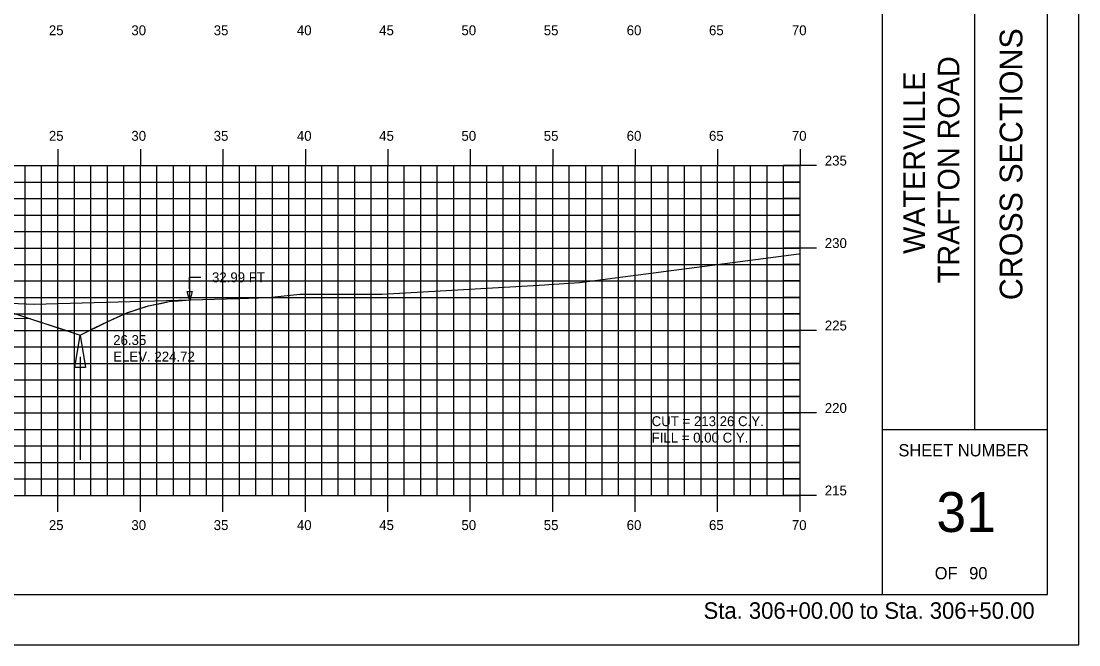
# Model space of a CAD drawing. Extents: x 1137433 to 1137603, y 608981 to 609091.
# Drawn here: x 1137538.4 to 1137602.6, y 608981.3 to 609019.1 of the extents above; entities that cross this region are included whole.
import ezdxf

# ---------------------------------------------------------------- set-up
doc = ezdxf.new("R2010")
doc.units = 0
for name, color, linetype in [('BORDER', 7, 'Continuous'), ('D_Drainage_Ditch_Line', 7, 'Continuous'), ('D_Roadway_SlopeLines', 7, 'Continuous'), ('D_Roadway_SubGrade', 7, 'Continuous'), ('D_Text_Standard', 7, 'Continuous'), ('H_V ANNOTATION', 7, 'Continuous'), ('HIGHWAY_TITLE', 7, 'Continuous'), ('MAJOR', 7, 'Continuous'), ('MINOR', 7, 'Continuous'), ('PLOT BOUNDARY', 7, 'Continuous'), ('S_Roadway_Centerline', 7, 'Continuous')]:
    doc.layers.add(name, color=color, linetype=linetype)

msp = doc.modelspace()

# ---------------------------------------------------------------- linework, layer by layer
msp.add_lwpolyline([(1137537.258, 609001.616), (1137538.984, 609001.048), (1137540.978, 609000.391), (1137542, 609000.054), (1137542.392, 609000.25), (1137542.83, 609000.469), (1137543.33, 609000.719), (1137543.627, 609000.867), (1137544.234, 609001.135), (1137544.886, 609001.422), (1137545.087, 609001.487), (1137545.504, 609001.621), (1137546.002, 609001.782), (1137546.144, 609001.827), (1137546.978, 609001.998), (1137547.403, 609002.084), (1137547.95, 609002.132), (1137548.662, 609002.193)])
at = {"layer": 'BORDER'}
for p, q in [((1137590.653, 608984.335), (1137590.653, 609089.335)), ((1137596.244, 608994.338), (1137596.244, 609029.338)), ((1137590.653, 608994.338), (1137600.653, 608994.338))]:
    msp.add_line(p, q, dxfattribs=at)
msp.add_lwpolyline([(1137440.653, 608984.335), (1137600.653, 608984.335), (1137600.653, 609089.335), (1137440.653, 609089.335)], close=True, dxfattribs=at)
at = {"layer": 'D_Drainage_Ditch_Line'}
msp.add_line((1137542, 608998.742), (1137542, 608992.499), dxfattribs=at)
msp.add_lwpolyline([(1137542.328, 608998.086), (1137541.672, 608998.086), (1137542, 609000.054)], close=True, dxfattribs=at)
at = {"layer": 'D_Roadway_SlopeLines'}
for points in [[(1137542, 609000.054), (1137543.628, 609000.867), (1137544.886, 609001.422), (1137546.144, 609001.827), (1137547.403, 609002.084), (1137548.662, 609002.193)], [(1137538.984, 609001.048), (1137542, 609000.054)]]:
    msp.add_lwpolyline(points, dxfattribs=at)
at = {"layer": 'D_Roadway_SubGrade'}
msp.add_lwpolyline([(1137526.653, 609003.36), (1137526.653, 609003.527), (1137530.966, 609003.44), (1137530.966, 609003.69), (1137530.966, 609003.69), (1137538.984, 609001.048), (1137526.653, 609001.277)], close=True, dxfattribs=at)
at = {"layer": 'D_Text_Standard'}
msp.add_lwpolyline([(1137548.644, 609002.125), (1137548.631, 609003.559), (1137549.311, 609003.559)], dxfattribs=at)
msp.add_lwpolyline([(1137548.644, 609002.125), (1137548.493, 609002.705), (1137548.784, 609002.708)], close=True, dxfattribs=at)
at = {"layer": 'MAJOR'}
for p, q in [((1137540.653, 609011.337), (1137540.653, 609010.335)), ((1137545.653, 609011.337), (1137545.653, 609010.335)), ((1137550.653, 609011.337), (1137550.653, 609010.335)), ((1137555.653, 609011.337), (1137555.653, 609010.335)), ((1137560.653, 609011.337), (1137560.653, 609010.335)), ((1137565.653, 609011.337), (1137565.653, 609010.335)), ((1137570.653, 609011.337), (1137570.653, 609010.335)), ((1137575.653, 609011.337), (1137575.653, 609010.335)), ((1137580.653, 609011.337), (1137580.653, 609010.335)), ((1137585.653, 609011.337), (1137585.653, 609010.335)), ((1137445.653, 609010.335), (1137585.653, 609010.335)), ((1137445.653, 609010.335), (1137585.653, 609010.335)), ((1137540.653, 608990.335), (1137540.653, 609010.335)), ((1137545.653, 608990.335), (1137545.653, 609010.335)), ((1137550.653, 608990.335), (1137550.653, 609010.335)), ((1137555.653, 608990.335), (1137555.653, 609010.335)), ((1137560.653, 608990.335), (1137560.653, 609010.335)), ((1137565.653, 608990.335), (1137565.653, 609010.335)), ((1137570.653, 608990.335), (1137570.653, 609010.335)), ((1137575.653, 608990.335), (1137575.653, 609010.335)), ((1137580.653, 608990.335), (1137580.653, 609010.335)), ((1137586.655, 609010.335), (1137584.651, 609010.335)), ((1137585.653, 608990.335), (1137585.653, 609010.335)), ((1137585.653, 608990.335), (1137585.653, 609010.335)), ((1137445.653, 609005.335), (1137585.653, 609005.335)), ((1137586.655, 609005.335), (1137584.651, 609005.335)), ((1137445.653, 609000.335), (1137585.653, 609000.335)), ((1137586.655, 609000.335), (1137584.651, 609000.335)), ((1137445.653, 608995.335), (1137585.653, 608995.335)), ((1137586.655, 608995.335), (1137584.651, 608995.335)), ((1137445.653, 608990.335), (1137585.653, 608990.335)), ((1137445.653, 608990.335), (1137585.653, 608990.335)), ((1137540.653, 608989.333), (1137540.653, 608990.335)), ((1137545.653, 608989.333), (1137545.653, 608990.335)), ((1137550.653, 608989.333), (1137550.653, 608990.335)), ((1137555.653, 608989.333), (1137555.653, 608990.335)), ((1137560.653, 608989.333), (1137560.653, 608990.335)), ((1137565.653, 608989.333), (1137565.653, 608990.335)), ((1137570.653, 608989.333), (1137570.653, 608990.335)), ((1137575.653, 608989.333), (1137575.653, 608990.335)), ((1137580.653, 608989.333), (1137580.653, 608990.335)), ((1137586.655, 608990.335), (1137584.651, 608990.335)), ((1137585.653, 608989.333), (1137585.653, 608990.335))]:
    msp.add_line(p, q, dxfattribs=at)
at = {"layer": 'MINOR'}
for p, q in [((1137538.653, 608990.335), (1137538.653, 609010.335)), ((1137539.653, 608990.335), (1137539.653, 609010.335)), ((1137541.653, 608990.335), (1137541.653, 609010.335)), ((1137542.653, 608990.335), (1137542.653, 609010.335)), ((1137543.653, 608990.335), (1137543.653, 609010.335)), ((1137544.653, 608990.335), (1137544.653, 609010.335)), ((1137546.653, 608990.335), (1137546.653, 609010.335)), ((1137547.653, 608990.335), (1137547.653, 609010.335)), ((1137548.653, 608990.335), (1137548.653, 609010.335)), ((1137549.653, 608990.335), (1137549.653, 609010.335)), ((1137551.653, 608990.335), (1137551.653, 609010.335)), ((1137552.653, 608990.335), (1137552.653, 609010.335)), ((1137553.653, 608990.335), (1137553.653, 609010.335)), ((1137554.653, 608990.335), (1137554.653, 609010.335)), ((1137556.653, 608990.335), (1137556.653, 609010.335)), ((1137557.653, 608990.335), (1137557.653, 609010.335)), ((1137558.653, 608990.335), (1137558.653, 609010.335)), ((1137559.653, 608990.335), (1137559.653, 609010.335)), ((1137561.653, 608990.335), (1137561.653, 609010.335)), ((1137562.653, 608990.335), (1137562.653, 609010.335)), ((1137563.653, 608990.335), (1137563.653, 609010.335)), ((1137564.653, 608990.335), (1137564.653, 609010.335)), ((1137566.653, 608990.335), (1137566.653, 609010.335)), ((1137567.653, 608990.335), (1137567.653, 609010.335)), ((1137568.653, 608990.335), (1137568.653, 609010.335)), ((1137569.653, 608990.335), (1137569.653, 609010.335)), ((1137571.653, 608990.335), (1137571.653, 609010.335)), ((1137572.653, 608990.335), (1137572.653, 609010.335)), ((1137573.653, 608990.335), (1137573.653, 609010.335)), ((1137574.653, 608990.335), (1137574.653, 609010.335)), ((1137576.653, 608990.335), (1137576.653, 609010.335)), ((1137577.653, 608990.335), (1137577.653, 609010.335)), ((1137578.653, 608990.335), (1137578.653, 609010.335)), ((1137579.653, 608990.335), (1137579.653, 609010.335)), ((1137581.653, 608990.335), (1137581.653, 609010.335)), ((1137582.653, 608990.335), (1137582.653, 609010.335)), ((1137583.653, 608990.335), (1137583.653, 609010.335)), ((1137584.653, 608990.335), (1137584.653, 609010.335)), ((1137445.653, 609009.335), (1137585.653, 609009.335)), ((1137585.653, 609009.335), (1137584.651, 609009.335)), ((1137445.653, 609008.335), (1137585.653, 609008.335)), ((1137585.653, 609008.335), (1137584.651, 609008.335)), ((1137445.653, 609007.335), (1137585.653, 609007.335)), ((1137585.653, 609007.335), (1137584.651, 609007.335)), ((1137445.653, 609006.335), (1137585.653, 609006.335)), ((1137585.653, 609006.335), (1137584.651, 609006.335)), ((1137445.653, 609004.335), (1137585.653, 609004.335)), ((1137585.653, 609004.335), (1137584.651, 609004.335)), ((1137445.653, 609003.335), (1137585.653, 609003.335)), ((1137585.653, 609003.335), (1137584.651, 609003.335)), ((1137445.653, 609002.335), (1137585.653, 609002.335)), ((1137585.653, 609002.335), (1137584.651, 609002.335)), ((1137445.653, 609001.335), (1137585.653, 609001.335)), ((1137585.653, 609001.335), (1137584.651, 609001.335)), ((1137445.653, 608999.335), (1137585.653, 608999.335)), ((1137585.653, 608999.335), (1137584.651, 608999.335)), ((1137445.653, 608998.335), (1137585.653, 608998.335)), ((1137585.653, 608998.335), (1137584.651, 608998.335)), ((1137445.653, 608997.335), (1137585.653, 608997.335)), ((1137585.653, 608997.335), (1137584.651, 608997.335)), ((1137445.653, 608996.335), (1137585.653, 608996.335)), ((1137585.653, 608996.335), (1137584.651, 608996.335)), ((1137445.653, 608994.335), (1137585.653, 608994.335)), ((1137585.653, 608994.335), (1137584.651, 608994.335)), ((1137445.653, 608993.335), (1137585.653, 608993.335)), ((1137585.653, 608993.335), (1137584.651, 608993.335)), ((1137445.653, 608992.335), (1137585.653, 608992.335)), ((1137585.653, 608992.335), (1137584.651, 608992.335)), ((1137445.653, 608991.335), (1137585.653, 608991.335)), ((1137585.653, 608991.335), (1137584.651, 608991.335))]:
    msp.add_line(p, q, dxfattribs=at)
at = {"layer": 'PLOT BOUNDARY'}
msp.add_lwpolyline([(1137432.56, 608981.276), (1137602.56, 608981.276), (1137602.56, 609091.276), (1137432.56, 609091.276)], close=True, dxfattribs=at)
at = {"layer": 'S_Roadway_Centerline'}
msp.add_lwpolyline([(1137526.981, 609002.445), (1137539.217, 609001.937), (1137551.599, 609002.272), (1137553.411, 609002.326), (1137555.311, 609002.546), (1137560.316, 609002.545), (1137570.169, 609003.109), (1137570.418, 609003.121), (1137572.272, 609003.244), (1137585.573, 609004.976), (1137585.653, 609004.985)], dxfattribs=at)

# ---------------------------------------------------------------- texts
at = {"layer": 'BORDER'}
msp.add_text('CROSS SECTIONS', height=1.37787, rotation=90, dxfattribs=at).set_placement((1137599.138, 609002.172))
for s, height, p in [('SHEET NUMBER', 0.74527, (1137591.619, 608992.701)), ('31', 2.4194, (1137593.924, 608988.118)), ('OF', 0.7453, (1137593.82, 608985.248)), ('90', 0.7453, (1137595.91, 608985.248))]:
    msp.add_text(s, height=height, dxfattribs=at).set_placement(p)
at = {"layer": 'D_Text_Standard'}
for s, p in [('32.99 FT', (1137549.991, 609003.259)), ('26.35', (1137544, 608999.454)), ('ELEV. 224.72', (1137544, 608998.452)), ('CUT = 213.26 C.Y.', (1137576.653, 608994.535)), ('FILL = 0.00 C.Y.', (1137576.653, 608993.539))]:
    msp.add_text(s, height=0.6, dxfattribs=at).set_placement(p)
at = {"layer": 'H_V ANNOTATION'}
for s, height, p in [('25', 0.6, (1137540.099, 609018.235)), ('30', 0.6, (1137545.102, 609018.235)), ('35', 0.6, (1137550.094, 609018.235)), ('40', 0.6, (1137555.139, 609018.235)), ('45', 0.6, (1137560.131, 609018.235)), ('50', 0.6, (1137565.118, 609018.235)), ('55', 0.6, (1137570.11, 609018.235)), ('60', 0.6, (1137575.139, 609018.235)), ('65', 0.6, (1137580.131, 609018.235)), ('70', 0.6, (1137585.155, 609018.235)), ('25', 0.6, (1137540.099, 609011.835)), ('30', 0.6, (1137545.102, 609011.835)), ('35', 0.6, (1137550.094, 609011.835)), ('40', 0.6, (1137555.139, 609011.835)), ('45', 0.6, (1137560.131, 609011.835)), ('50', 0.6, (1137565.118, 609011.835)), ('55', 0.6, (1137570.11, 609011.835)), ('60', 0.6, (1137575.139, 609011.835)), ('65', 0.6, (1137580.131, 609011.835)), ('70', 0.6, (1137585.155, 609011.835)), ('235', 0.6, (1137587.153, 609010.335)), ('230', 0.6, (1137587.153, 609005.335)), ('225', 0.6, (1137587.153, 609000.335)), ('220', 0.6, (1137587.153, 608995.335)), ('215', 0.6, (1137587.153, 608990.335)), ('25', 0.6, (1137540.099, 608988.235)), ('30', 0.6, (1137545.102, 608988.235)), ('35', 0.6, (1137550.094, 608988.235)), ('40', 0.6, (1137555.139, 608988.235)), ('45', 0.6, (1137560.131, 608988.235)), ('50', 0.6, (1137565.118, 608988.235)), ('55', 0.6, (1137570.11, 608988.235)), ('60', 0.6, (1137575.139, 608988.235)), ('65', 0.6, (1137580.131, 608988.235)), ('70', 0.6, (1137585.155, 608988.235)), ('Sta. 306+00.00 to Sta. 306+50.00', 1.0002, (1137579.799, 608982.855))]:
    msp.add_text(s, height=height, dxfattribs=at).set_placement(p)
at = {"layer": 'HIGHWAY_TITLE'}
for s, height, p in [('TRAFTON ROAD', 1.30428, (1137595.312, 609003.201)), ('WATERVILLE', 1.3043, (1137593.225, 609004.98))]:
    msp.add_text(s, height=height, rotation=90, dxfattribs=at).set_placement(p)

doc.saveas('drawing.dxf')
